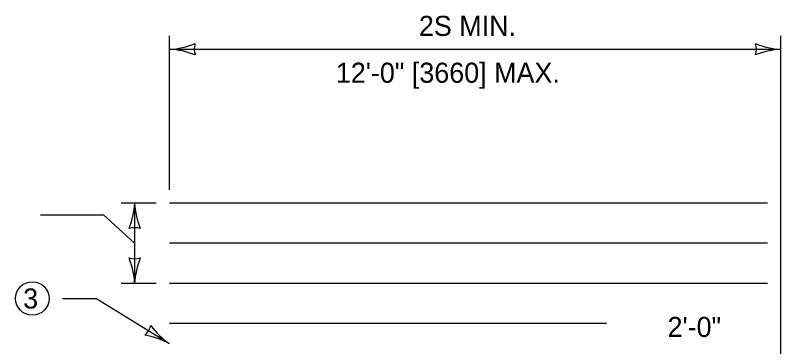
# Model space of a CAD drawing. Extents: x 49991.4 to 50021, y 49987.6 to 50011.4.
# Drawn here: x 50006.46 to 50008.777, y 49993.799 to 49994.788 of the extents above; entities that cross this region are included whole.
import ezdxf

# ---------------------------------------------------------------- set-up
doc = ezdxf.new("R2010")
doc.units = 0
for name, color, linetype in [('Level 1', 7, 'Continuous'), ('Level 2', 7, 'Continuous'), ('Level 3', 7, 'Continuous')]:
    doc.layers.add(name, color=color, linetype=linetype)

msp = doc.modelspace()

# ---------------------------------------------------------------- linework, layer by layer
at = {"layer": 'Level 1'}
for p, q in [((50008.7031, 49994.2278), (50006.9193, 49994.2278)), ((50008.7031, 49994.1078), (50006.9193, 49994.1078)), ((50008.7031, 49993.9878), (50006.9193, 49993.9878)), ((50008.2231, 49993.8678), (50006.9193, 49993.8678))]:
    msp.add_line(p, q, dxfattribs=at)
msp.add_ellipse((50009.2585, 49993.4847), major_axis=(-0.5152, -0.0149), ratio=0.976362, start_param=4.796646, end_param=6.264407, dxfattribs=at)
at = {"layer": 'Level 2'}
msp.add_circle((50006.51, 49993.9428), 0.05, dxfattribs=at)
at = {"layer": 'Level 3'}
for p, q in [((50006.9193, 49994.2678), (50006.9193, 49994.7274)), ((50008.7431, 49993.6478), (50008.7431, 49994.7274)), ((50006.9193, 49994.6874), (50008.7431, 49994.6874)), ((50006.8793, 49994.2278), (50006.7753, 49994.2278)), ((50006.8793, 49994.2278), (50006.7753, 49994.2278)), ((50006.8153, 49994.2278), (50006.8153, 49993.9878)), ((50006.8153, 49994.2278), (50006.8153, 49993.9878)), ((50006.5348, 49994.1928), (50006.7224, 49994.1928)), ((50006.8153, 49994.1078), (50006.7224, 49994.1928)), ((50006.8793, 49993.9878), (50006.7753, 49993.9878)), ((50006.8793, 49993.9878), (50006.7753, 49993.9878)), ((50006.6, 49993.9428), (50006.6999, 49993.9428)), ((50006.6, 49993.9428), (50006.6999, 49993.9428)), ((50006.9193, 49993.8078), (50006.6999, 49993.9428))]:
    msp.add_line(p, q, dxfattribs=at)
for centre, radius, start, end in [((50006.9078, 49994.9202), 0.233, 272.8273, 292.0772), ((50007.0475, 49994.6874), 0.0548, 162.1388, 197.8612), ((50008.7523, 49994.9096), 0.2223, 247.456, 267.6395), ((50008.6149, 49994.6874), 0.0548, 342.1388, 17.8612), ((50006.9101, 49994.4653), 0.2223, 67.456, 87.6395), ((50008.7546, 49994.4547), 0.233, 92.8273, 112.0772), ((50006.5826, 49994.2393), 0.233, 337.9228, 357.1727), ((50006.5826, 49994.2393), 0.233, 337.9228, 357.1727), ((50007.0374, 49994.2369), 0.2223, 182.3605, 202.544), ((50007.0374, 49994.2369), 0.2223, 182.3605, 202.544), ((50006.8153, 49994.0996), 0.0548, 72.1388, 107.8612), ((50006.8153, 49994.0996), 0.0548, 72.1388, 107.8612), ((50006.5931, 49993.9786), 0.2223, 2.3605, 22.544), ((50006.8153, 49994.116), 0.0548, 252.1388, 287.8612), ((50006.5931, 49993.9786), 0.2223, 2.3605, 22.544), ((50006.8153, 49994.116), 0.0548, 252.1388, 287.8612), ((50007.048, 49993.9763), 0.233, 157.9228, 177.1727), ((50007.048, 49993.9763), 0.233, 157.9228, 177.1727), ((50006.8101, 49993.875), 0.0548, 310.5238, 346.2462), ((50007.0435, 49993.9922), 0.2223, 215.841, 236.0245), ((50006.8071, 49993.6036), 0.233, 61.2123, 80.4621)]:
    msp.add_arc(centre, radius, start, end, dxfattribs=at)

# ---------------------------------------------------------------- texts
at = {"layer": 'Level 2'}
for s, p in [('2S MIN.', (50007.6631, 49994.7274)), ('12\'-0" [3660] MAX.', (50007.4154, 49994.5874)), ('3', (50006.4827, 49993.9128)), ('2\'-0"', (50008.4048, 49993.8278))]:
    msp.add_text(s, height=0.06, dxfattribs=at).set_placement(p)

doc.saveas('drawing.dxf')
